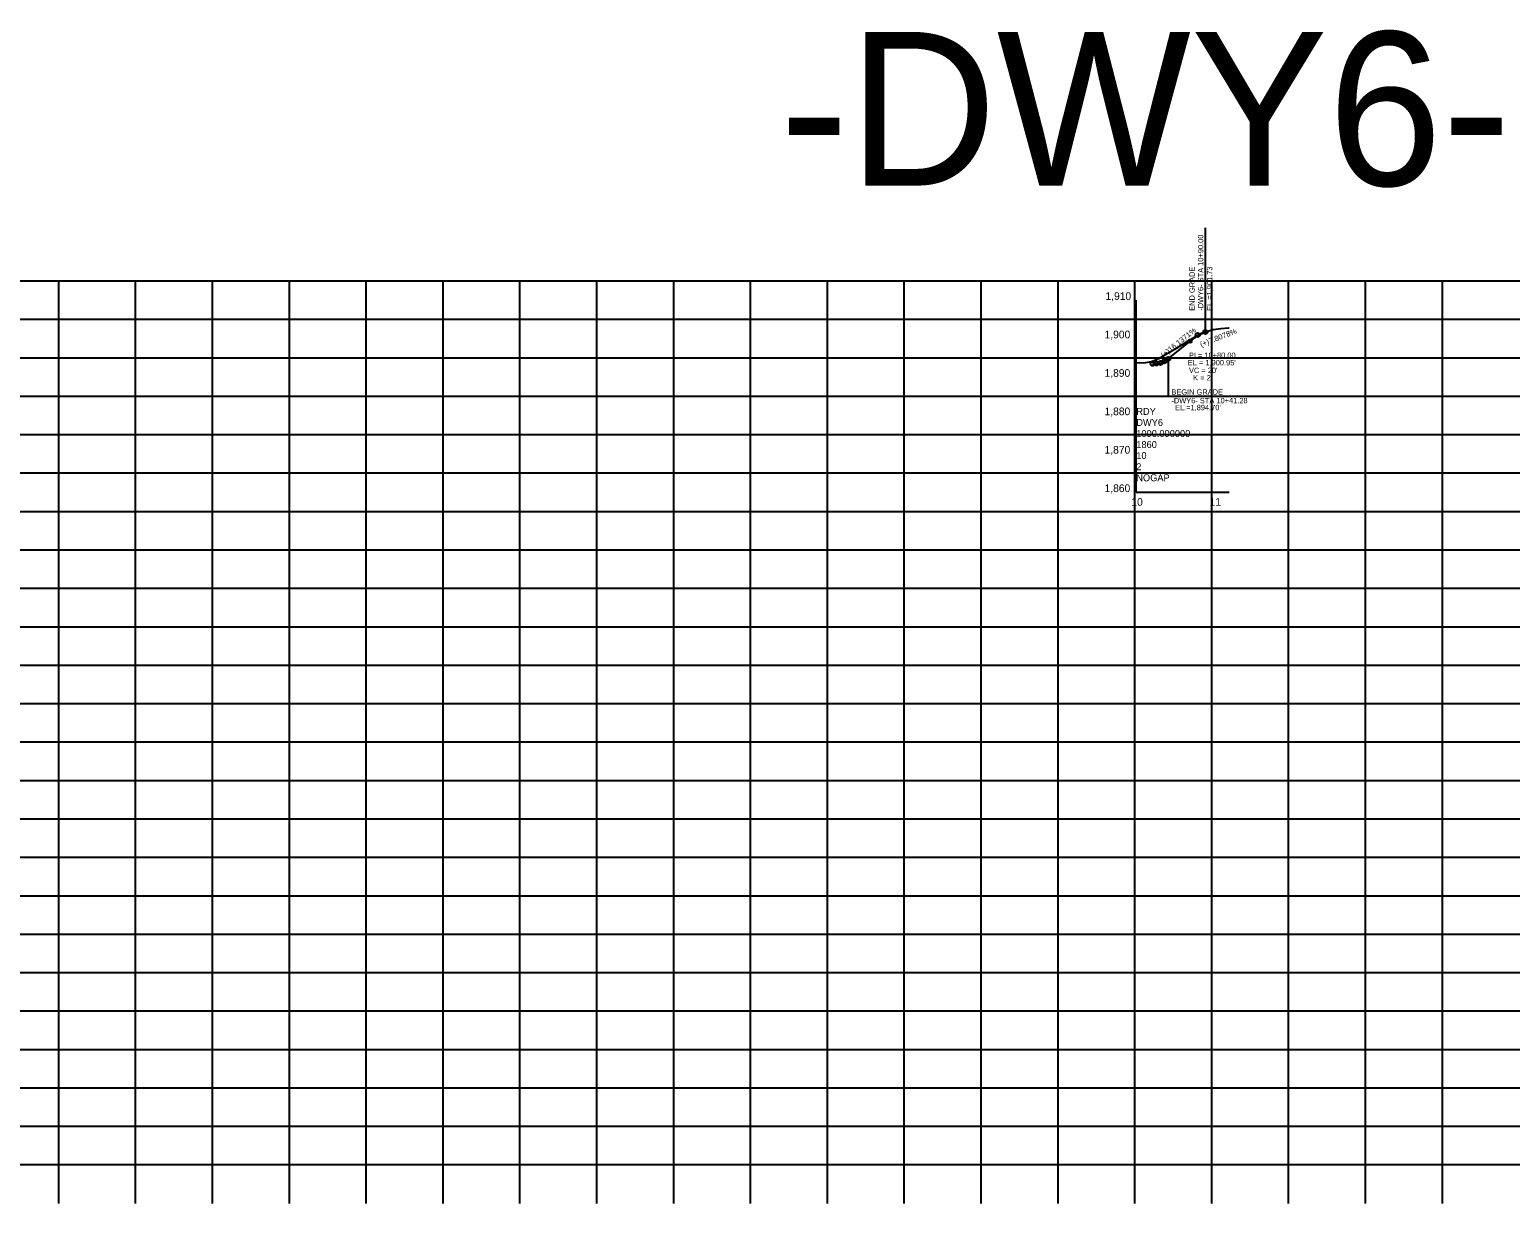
# Model space of a CAD drawing. Extents: x 553912 to 567693, y 512355 to 537539.
# Drawn here: x 558812 to 560738, y 533917 to 535444 of the extents above; entities that cross this region are included whole.
import ezdxf

# ---------------------------------------------------------------- set-up
doc = ezdxf.new("R2010")
doc.units = 0
for name, color, linetype in [('Exist Profile Cell', 7, 'Continuous'), ('Exist Vertical Profile Ground Line', 7, 'Continuous'), ('Exist Vertical Profile Horizontal Axis Label Major', 7, 'Continuous'), ('Exist Vertical Profile Vertical Axis Label', 7, 'Continuous'), ('Prop EOT', 7, 'Continuous'), ('Prop Vertical Profile Curve Label', 7, 'Continuous'), ('Prop Vertical Profile Grade', 7, 'Continuous'), ('Prop Vertical Profile Grade Label', 7, 'Continuous'), ('Prop VPI Label', 7, 'Continuous'), ('Sheet Profile Grid Major CELL', 7, 'Continuous')]:
    doc.layers.add(name, color=color, linetype=linetype)

msp = doc.modelspace()

# ---------------------------------------------------------------- linework, layer by layer
at = {"layer": 'Exist Profile Cell'}
for q in [(560251.3, 535092.1), (560372, 534842.1), (560251.3, 534842.1)]:
    msp.add_line((560251.3, 534842.1), q, dxfattribs=at)
at = {"layer": 'Exist Vertical Profile Ground Line'}
msp.add_lwpolyline([(560251.3, 535010.9), (560261.3, 535010.5), (560271.3, 535012.1), (560281.3, 535016.8), (560291.3, 535022.5), (560301.3, 535028.3), (560311.3, 535034.6), (560321.3, 535040.9), (560331.3, 535046.7), (560341.3, 535050.7), (560351.3, 535054.1), (560361.3, 535055.1), (560371.3, 535056), (560372, 535056.1)], dxfattribs=at)
at = {"layer": 'Prop Vertical Profile Curve Label'}
for centre in [(560321.3, 535038.8), (560341.3, 535050.7)]:
    msp.add_circle(centre, 2.25, dxfattribs=at)
at = {"layer": 'Prop Vertical Profile Grade'}
for p, q in [((560292.6, 535015.6), (560321.3, 535038.8)), ((560272.6, 535009.3), (560277.6, 535009.8)), ((560277.6, 535009.8), (560282.6, 535010.3)), ((560282.6, 535010.3), (560287.6, 535012.5)), ((560287.6, 535012.5), (560292.6, 535015.6))]:
    msp.add_line(p, q, dxfattribs=at)
msp.add_spline([(560321.3, 535038.8), (560321.7, 535039.1), (560322.1, 535039.4), (560322.5, 535039.7), (560322.9, 535040), (560323.3, 535040.3), (560323.7, 535040.7), (560324.1, 535041), (560324.5, 535041.3), (560324.9, 535041.5), (560325.3, 535041.8), (560325.7, 535042.1), (560326.1, 535042.4), (560326.5, 535042.7), (560326.9, 535043), (560327.3, 535043.2), (560327.7, 535043.5), (560328.1, 535043.8), (560328.5, 535044), (560328.9, 535044.3), (560329.3, 535044.6), (560329.7, 535044.8), (560330.1, 535045.1), (560330.5, 535045.3), (560330.9, 535045.6), (560331.3, 535045.8), (560331.7, 535046), (560332.1, 535046.3), (560332.5, 535046.5), (560332.9, 535046.7), (560333.3, 535047), (560333.7, 535047.2), (560334.1, 535047.4), (560334.5, 535047.6), (560334.9, 535047.8), (560335.3, 535048), (560335.7, 535048.2), (560336.1, 535048.4), (560336.5, 535048.6), (560336.9, 535048.8), (560337.3, 535049), (560337.7, 535049.2), (560338.1, 535049.4), (560338.5, 535049.6), (560338.9, 535049.8), (560339.3, 535049.9), (560339.7, 535050.1), (560340.1, 535050.3), (560340.5, 535050.4), (560340.9, 535050.6), (560341.3, 535050.7)], degree=3, dxfattribs=at)
at = {"layer": 'Prop VPI Label'}
for p, q in [((560341.3, 535050.7), (560341.3, 535186.3)), ((560321.3, 535038.8), (560329.2, 535045.1)), ((560341.3, 535050.7), (560333.9, 535047.8)), ((560292.6, 535015.6), (560292.6, 534967.2)), ((560292.6, 534967.2), (560403.9, 534967.2))]:
    msp.add_line(p, q, dxfattribs=at)
for centre in [(560331.3, 535046.8), (560341.3, 535050.7), (560272.6, 535009.3), (560277.6, 535009.8), (560282.6, 535010.3), (560287.6, 535012.5), (560292.6, 535015.6)]:
    msp.add_circle(centre, 2.75, dxfattribs=at)
at = {"layer": 'Sheet Profile Grid Major CELL'}
for p, q in [((563849.5, 535116.8), (557249.5, 535116.8)), ((558849.5, 533916.8), (558849.5, 535116.8)), ((558949.5, 533916.8), (558949.5, 535116.8)), ((559049.5, 533916.8), (559049.5, 535116.8)), ((559149.5, 533916.8), (559149.5, 535116.8)), ((559249.5, 533916.8), (559249.5, 535116.8)), ((559349.5, 533916.8), (559349.5, 535116.8)), ((559449.5, 533916.8), (559449.5, 535116.8)), ((559549.5, 533916.8), (559549.5, 535116.8)), ((559649.5, 533916.8), (559649.5, 535116.8)), ((559749.5, 533916.8), (559749.5, 535116.8)), ((559849.5, 533916.8), (559849.5, 535116.8)), ((559949.5, 533916.8), (559949.5, 535116.8)), ((560049.5, 533916.8), (560049.5, 535116.8)), ((560149.5, 533916.8), (560149.5, 535116.8)), ((560249.5, 533916.8), (560249.5, 535116.8)), ((560349.5, 533916.8), (560349.5, 535116.8)), ((560449.5, 533916.8), (560449.5, 535116.8)), ((560549.5, 533916.8), (560549.5, 535116.8)), ((560649.5, 533916.8), (560649.5, 535116.8)), ((563849.5, 535066.8), (557249.5, 535066.8)), ((563849.5, 535016.8), (557249.5, 535016.8)), ((563849.5, 534966.8), (557249.5, 534966.8)), ((563849.5, 534916.8), (557249.5, 534916.8)), ((563849.5, 534866.8), (557249.5, 534866.8)), ((563849.5, 534816.8), (557249.5, 534816.8)), ((563849.5, 534766.8), (557249.5, 534766.8)), ((563849.5, 534716.8), (557249.5, 534716.8)), ((563849.5, 534666.8), (557249.5, 534666.8)), ((563849.5, 534616.8), (557249.5, 534616.8)), ((563849.5, 534566.8), (557249.5, 534566.8)), ((563849.5, 534516.8), (557249.5, 534516.8)), ((563849.5, 534466.8), (557249.5, 534466.8)), ((563849.5, 534416.8), (557249.5, 534416.8)), ((563849.5, 534366.8), (557249.5, 534366.8)), ((563849.5, 534316.8), (557249.5, 534316.8)), ((563849.5, 534266.8), (557249.5, 534266.8)), ((563849.5, 534216.8), (557249.5, 534216.8)), ((563849.5, 534166.8), (557249.5, 534166.8)), ((563849.5, 534116.8), (557249.5, 534116.8)), ((563849.5, 534066.8), (557249.5, 534066.8)), ((563849.5, 534016.8), (557249.5, 534016.8)), ((563849.5, 533966.8), (557249.5, 533966.8))]:
    msp.add_line(p, q, dxfattribs=at)

# ---------------------------------------------------------------- texts
at = {"layer": 'Exist Profile Cell'}
for s, p in [('RDY', (560251.3, 534942.9)), ('1000.000000', (560251.3, 534914.1)), ('DWY6', (560251.3, 534928.5)), ('1860', (560251.3, 534899.7)), ('10', (560251.3, 534885.3)), ('2', (560251.3, 534870.9)), ('NOGAP', (560251.3, 534856.5))]:
    msp.add_text(s, height=9, dxfattribs=at).set_placement(p)
at = {"layer": 'Exist Vertical Profile Horizontal Axis Label Major'}
for s, p in [('10', (560244.9, 534824.6)), ('11', (560346.7, 534824.6))]:
    msp.add_text(s, height=10, dxfattribs=at).set_placement(p)
at = {"layer": 'Exist Vertical Profile Vertical Axis Label'}
for s, p in [('1,910', (560211.2, 535092.4)), ('1,900', (560210, 535042.4)), ('1,890', (560210, 534992.4)), ('1,880', (560210, 534942.4)), ('1,870', (560210, 534892.4)), ('1,860', (560210, 534842.4))]:
    msp.add_text(s, height=10, dxfattribs=at).set_placement(p)
at = {"layer": 'Prop EOT'}
msp.add_text('-DWY6-', height=200, dxfattribs=at).set_placement((559787.6, 535241.2))
at = {"layer": 'Prop Vertical Profile Curve Label'}
for s, p in [("VC = 20'", (560319.9, 534997.3)), ('K = 2', (560325.3, 534987.6))]:
    msp.add_text(s, height=7, dxfattribs=at).set_placement(p)
at = {"layer": 'Prop Vertical Profile Grade Label'}
for s, rotation, p in [('(+)16.1371%', 38.8985, (560286.6, 535016.8)), ('(+)7.8078%', 21.3251, (560335.8, 535030.9))]:
    msp.add_text(s, height=7, rotation=rotation, dxfattribs=at).set_placement(p)
at = {"layer": 'Prop VPI Label'}
for s, rotation, p in [('-DWY6- STA 10+90.00', 90, (560338.5, 535078.3)), ('END GRADE', 90, (560327.3, 535078.3)), ('EL.=1,901.73', 90, (560350.2, 535078.1)), ('-DWY6- STA 10+41.28', 360, (560297, 534957.9)), ('BEGIN GRADE', 360, (560297, 534969.1)), ("EL.=1,894.70'", 360, (560301.7, 534948.9))]:
    msp.add_text(s, height=7, rotation=rotation, dxfattribs=at).set_placement(p)
for s, p in [('PI = 10+80.00', (560319.8, 535016.9)), ("EL = 1,900.95'", (560318.4, 535007.3))]:
    msp.add_text(s, height=7, dxfattribs=at).set_placement(p)

doc.saveas('drawing.dxf')
